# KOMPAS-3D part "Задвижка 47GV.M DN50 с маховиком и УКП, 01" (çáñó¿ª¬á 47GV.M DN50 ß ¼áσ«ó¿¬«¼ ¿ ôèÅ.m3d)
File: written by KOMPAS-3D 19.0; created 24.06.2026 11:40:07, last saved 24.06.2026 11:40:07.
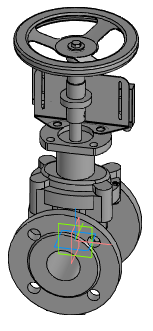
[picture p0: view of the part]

Document properties: Автор: Евгений; Полное имя файла: ..\47GV.M DN50\Задвижка 47GV.M DN50 с маховиком и УКП.a3d

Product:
- Part/product: Задвижка 47GV.M DN50 с маховиком и УКП  | designation 01
    Масса: 10.055
  - Component [detail]: Корпус  | pos. 3  | Материал: ВЧ50 ГОСТ 7293-85 (density 7200 kg/m3); Масса: 8.77519; Раздел спецификации: Детали; Форматы листов документа: 2xA3; source file: ..\47GV.M DN50\DR.47GVM.050.16.00.001 - Корпус.cdw, ..\47GV.M DN50\Корпус 47GV.M DN50.m3d
  - Component [assembly]: Клин с направляющими  | designation DR.47GVM.050.16.01.000  | pos. 4  | Раздел спецификации: Сборочные единицы; Форматы листов документа: A4; source file: ..\47GV.M DN50\DR.47GVM.050.16.01.000  - Клин с направляющими.a3d, ..\47GV.M DN50\DR.47GVM.050.16.01.000  - Клин с направляющими.spw, ..\47GV.M DN50\DR.47GVM.050.16.01.000  СБ - Клин с направляющими.cdw
  - Component [detail]: Крышка  | pos. 4  | Материал: ВЧ50 ГОСТ 7293-85 (density 7200 kg/m3); Масса: 2.87085; Раздел спецификации: Детали; source file: ..\47GV.M DN50\DR.47GVM.050.16.00.002 - Крышка.cdw, ..\47GV.M DN50\Крышка 47GV.M DN50.m3d
  - Component [detail]: Шпиндель УКП  | pos. 5  | Материал: Сталь 20Х13 ГОСТ 5632-2014 (density 7670 kg/m3); Масса: 0.296937; Раздел спецификации: Детали; source file: ..\47GV.M DN50\DR.47GVM.050.16.00.003 - Шпиндель.cdw, ..\47GV.M DN50\Шпиндель 47GV.M DN50 для УКП.m3d
  - Component [detail]: Маховик 180  | pos. 20  | Масса: 0.393105; Раздел спецификации: Прочие изделия; source file: ..\47GV.M DN50\Маховик 180.m3d
  - Component [standard]: Шайба821695878  | pos. 16
      Материал: Сталь 12Х18Н10Т ГОСТ 5632-2014 (density 1000 kg/m3)
      Масса: 0.000793943
      Раздел спецификации: Стандартные изделия
      Примечание: См. п.6 ТТ
      Рассекать на разрезах: no
      additional columns: ГОСТ 6958-78; A 8.21
  - Component [standard]: Болт86g187798  | pos. 12  | Масса: 0.0123; Раздел спецификации: Стандартные изделия; Примечание: См. п.6 ТТ; Рассекать на разрезах: no; additional columns: ГОСТ 7798-70; М8-6gx18
  - Component: Насадка для УКП  | designation DR.47GVM.UKP.050.16.00.001  | Материал: Сталь 08Х18Н10 ГОСТ 5632-2014 (density 7900 kg/m3); Масса: 0.411057; Раздел спецификации: Детали; Форматы листов документа: A4; source file: ..\47GV.M DN50\DR.47GVM.UKP.050.16.00.001 - Насадка для УКП.cdw, ..\47GV.M DN50\DR.47GVM.UKP.050.16.00.001 Насадка для УКП.m3d, ..\47GV.M DN50\DR.47GVM.UKP.100.16.00.001 - Насадка для УКП.cdw
  - Component: Кронштейн  | designation DR.47GVM.UKP.050.16.00.002  | Материал: Ст3сп ГОСТ 380-2005 (density 7850 kg/m3); Масса: 0.148202; Раздел спецификации: Детали; Форматы листов документа: A3; source file: ..\47GV.M DN50\DR.47GVM.UKP.050.16.00.002 - Кронштейн.cdw, ..\47GV.M DN50\DR.47GVM.UKP.050.16.00.002 - Кронштейн.m3d, ..\47GV.M DN50\DR.47GVM.UKP.100.16.00.002 - Кронштейн.cdw
  - Component: Контргайка  | designation DR.47GVM.UKP.050.16.00.003  | Материал: Сталь 08Х18Н10 ГОСТ 5632-2014 (density 7900 kg/m3); Масса: 0.0897966; Раздел спецификации: Детали; Форматы листов документа: A4; source file: ..\47GV.M DN50\DR.47GVM.UKP.050.16.00.003 - Контргайка.cdw, ..\47GV.M DN50\DR.47GVM.UKP.050.16.00.003 - Контргайка.m3d, ..\47GV.M DN50\DR.47GVM.UKP.100.16.00.003 - Контргайка.cdw
  - Component: Винт установочный М6х45  | designation DR.47GVM.UKP.050.16.00.005  | Материал: Сталь 08Х18Н10 ГОСТ 5632-2014 (density 7900 kg/m3); Масса: 0.00994284; source file: ..\47GV.M DN50\DR.47GVM.UKP.050.16.00.005 Винт установочный.m3d
  - Component: Концевик AZ7311  | qty 2  | Масса: 0.377378; source file: ..\47GV.M DN50\Концевик AZ7311.m3d
- Part/product: Задвижка 47GV.M DN50 с маховиком и УКП
    Масса: 13.7684
    Раздел спецификации: Документация
    Форматы листов документа: 2xA3
  - Component: Задвижка с обрезиненным клином DN50. Сборочный чертеж  | designation DR.47GVM.050.16.00.000СБ  | pos. 0  | Масса: 10.0548; Раздел спецификации: Документация; Форматы листов документа: 2xA3; source file: ..\47GV.M DN50\DR.47GVM.050.16.00.000 СБ - Задвижка с обрезиненным клином DN100.cdw

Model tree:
1. Операция без истории:1

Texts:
  Точка начала. Х
  Точка начала. Y
  Точка начала. Z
